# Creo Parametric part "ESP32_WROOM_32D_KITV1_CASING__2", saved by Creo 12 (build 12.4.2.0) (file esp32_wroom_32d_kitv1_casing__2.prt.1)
Units: Custom; MM, KILOGRAM, SECS

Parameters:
  PTC_WM_ITERATION = "0"
  PTC_WM_VERSION = "-.0"
  PTC_WM_LIFECYCLE_STATE = "In Work"
  PTC_WM_LIFECYCLE = "MO_CADDocument"
  PTC_WM_CREATED_BY = "Maximilian Roepper (Z0017RMS: MO)"
  PTC_WM_CREATED_ON = "18-Sep-26 11:36:42 AM"
  PTC_WM_MODIFIED_BY = "Maximilian Roepper (Z0017RMS: MO)"
  PTC_WM_MODIFIED_ON = "18-Sep-26 11:36:46 AM"
  PDMLINKNUMBER = "PDM000071455201"
  PTC_WM_NAME = "esp32_wroom_32d_kitv1_casing__2.prt"
  PTC_WM_NUMBER = "PDM000071455201"

Other parameters: WEIGHT, WEIGHT_FACTOR, WEIGHT_ADD, _MASS_TEMP, _DIFF_TEMP, MC_ERRORS, SUPPLIER

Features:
  1. coordinate system
  2. datum plane "PRT_YZ"
  3. datum plane "PRT_XY"
  4. datum plane "PRT_XZ"
  5. coordinate system
  6. datum axis
  7. datum axis
  8. datum axis
  9. coordinate system
  10. imported feature
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
Other named items: PRT, SIEMENS_MO, DRW_VIEW_ORG, PRT_X, PRT_Y, PRT_Z, CS0, ROUGH_GROB

Layers: 00_STD_CSYS-KSYS, 01_STD_PLANES-EBENEN, 02_STD_AXES-ACHSEN, 03_STD_CSYS-KSYS, 24_IMPORT_FEAT-IMPORT_KE

Surfaces: 6 plane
